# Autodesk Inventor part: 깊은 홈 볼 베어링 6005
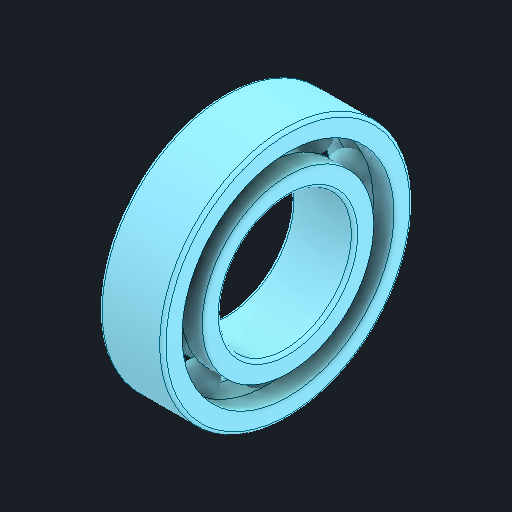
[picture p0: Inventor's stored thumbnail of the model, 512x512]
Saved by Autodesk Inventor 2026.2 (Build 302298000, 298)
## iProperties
Created: 2025-11
Part Number: 깊은 홈 볼 베어링 6005
Material: 강철, 연강
Description: 깊은 그루브 볼 베어링
Document SubType Name: Modeling
Designer: PC2-07
Density: 7.85 g/cm^3
Appearance: 기본값
Author: jhkim
Sending System: Autodesk Inventor 2026
Preprocessor: ST-DEVELOPER v20.1
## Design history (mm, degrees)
feature "Solid1"
feature "Solid1:1"
feature "Solid1:2"
feature "Solid1:3"
feature "Solid1:4"
feature "Solid1:5"
feature "Solid1:6"
feature "Solid1:7"
feature "Solid1:8"
feature "Solid1:9"
feature "Solid1:10"
feature "Solid1:11"
node "솔리드1"
node "솔리드2"
node "솔리드3"
node "솔리드4"
node "솔리드5"
node "솔리드6"
node "솔리드7"
node "솔리드8"
node "솔리드9"
node "솔리드10"
node "솔리드11"
node "솔리드12"
